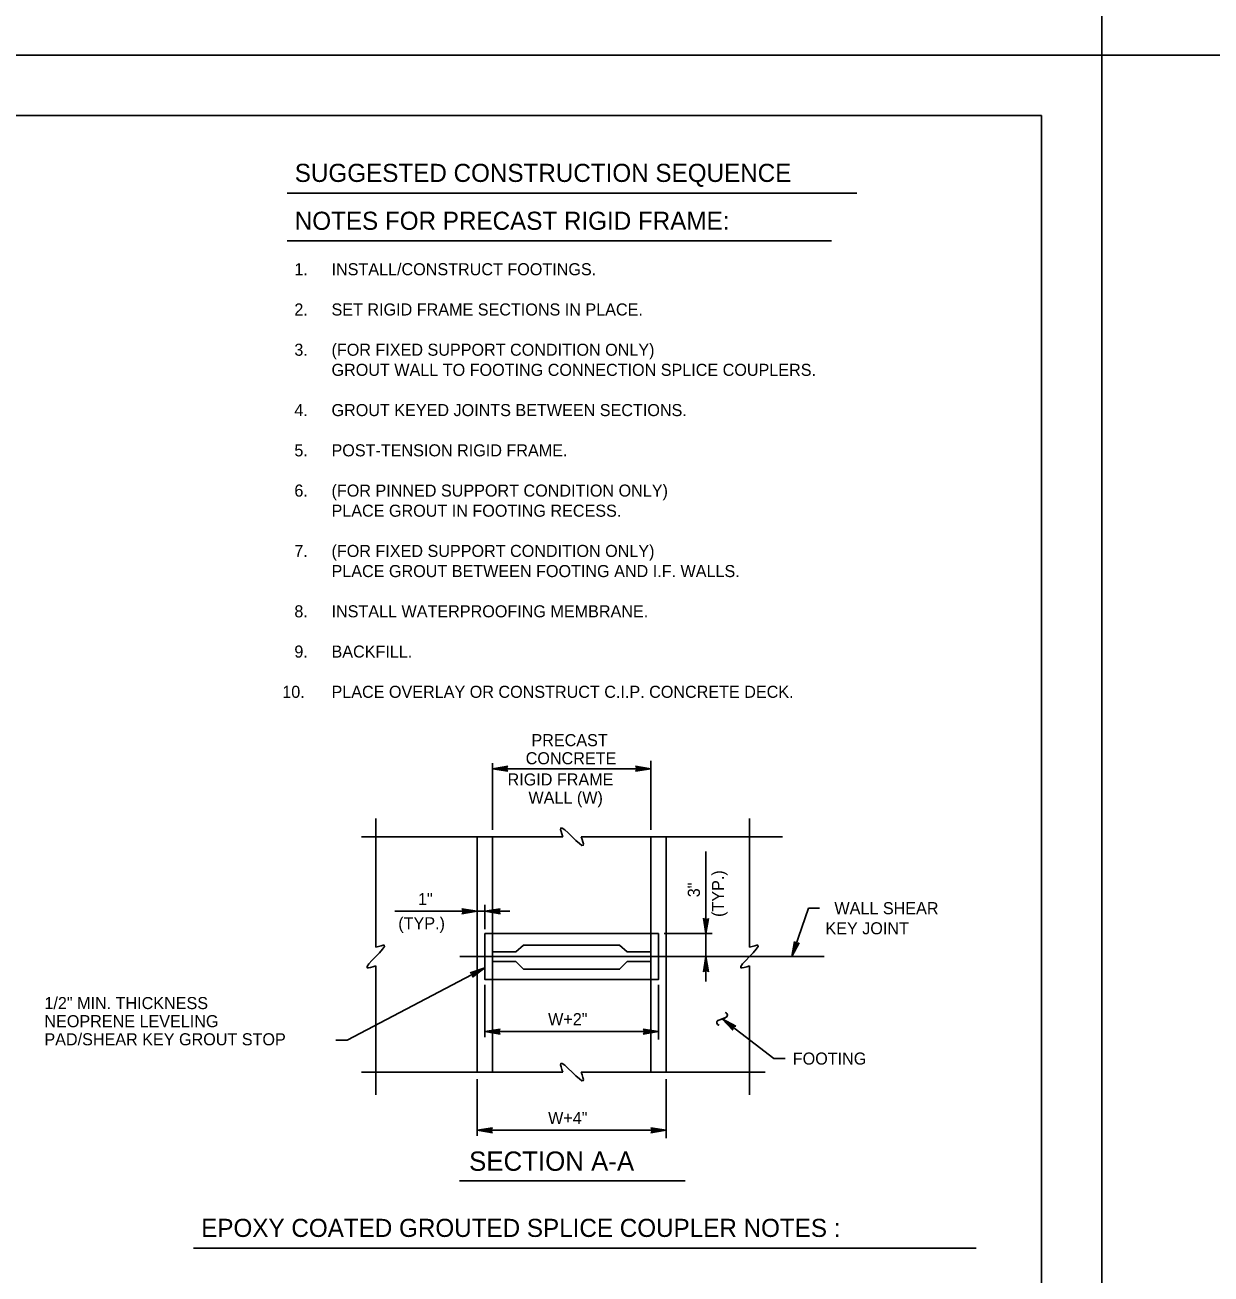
# Model space of a CAD drawing. Extents: x 641328 to 643024, y 298283 to 300065.
# Drawn here: x 641901 to 642195.6, y 299168.4 to 299478.8 of the extents above; entities that cross this region are included whole.
import ezdxf

# ---------------------------------------------------------------- set-up
doc = ezdxf.new("R2010")
doc.units = 0
for name, color, linetype in [('2', 7, 'Continuous'), ('PLT-BNDY', 7, 'Continuous'), ('S-ANNO-DIMENSION-PROP', 7, 'Continuous'), ('S-BRDG-CNTR-N', 7, 'Continuous')]:
    doc.layers.add(name, color=color, linetype=linetype)

msp = doc.modelspace()

# ---------------------------------------------------------------- linework, layer by layer
at = {"layer": '2'}
for p, q in [((641367.51, 299456.3), (642153.5, 299456.3)), ((642153.5, 299456.3), (642153.5, 298892.3)), ((641966.07, 299437.02), (642107.67, 299437.02)), ((641966.07, 299425.13), (642101.37, 299425.13)), ((642017.14, 299278.84), (642017.14, 299295.35)), ((642017.14, 299293.97), (642020.93, 299294.61)), ((642020.74, 299294.43), (642017.14, 299293.97)), ((642017.14, 299293.97), (642020.61, 299294.17)), ((642017.14, 299293.97), (642020.61, 299293.99)), ((642017.14, 299293.97), (642056.42, 299293.97)), ((642020.61, 299293.81), (642017.14, 299293.97)), ((642017.14, 299293.97), (642020.75, 299293.54)), ((642020.94, 299293.38), (642017.14, 299293.97)), ((642020.61, 299294.17), (642020.74, 299294.43)), ((642020.61, 299293.81), (642020.61, 299294.17)), ((642020.75, 299293.54), (642020.61, 299293.81)), ((642020.93, 299294.61), (642020.74, 299294.43)), ((642020.75, 299293.54), (642020.94, 299293.38)), ((642056.42, 299293.97), (642052.62, 299294.61)), ((642052.62, 299294.61), (642052.82, 299294.43)), ((642052.62, 299293.38), (642056.42, 299293.97)), ((642052.81, 299293.54), (642052.62, 299293.38)), ((642056.42, 299293.97), (642052.81, 299293.54)), ((642052.81, 299293.54), (642052.94, 299293.81)), ((642052.95, 299294.17), (642052.82, 299294.43)), ((642052.82, 299294.43), (642056.42, 299293.97)), ((642052.94, 299293.81), (642052.95, 299294.17)), ((642052.94, 299293.81), (642056.42, 299293.97)), ((642056.42, 299293.97), (642052.95, 299294.17)), ((642056.42, 299293.97), (642052.95, 299293.99)), ((642056.42, 299278.84), (642056.42, 299295.97)), ((641988.11, 299281.62), (641988.11, 299249.62)), ((642080.95, 299281.62), (642080.95, 299249.62)), ((642034.56, 299277.1), (641984.56, 299277.1)), ((642013.33, 299277.1), (642013.33, 299218.61)), ((642017.14, 299277.1), (642013.33, 299277.1)), ((642013.33, 299277.1), (642013.33, 299218.61)), ((642017.14, 299277.1), (642017.14, 299218.61)), ((642017.14, 299253.02), (642017.14, 299277.1)), ((642089.18, 299277.1), (642039.18, 299277.1)), ((642056.42, 299277.1), (642056.42, 299218.61)), ((642060.23, 299277.1), (642056.42, 299277.1)), ((642056.42, 299277.1), (642056.42, 299253.02)), ((642060.23, 299218.61), (642060.23, 299277.1)), ((642060.23, 299218.61), (642060.23, 299277.1)), ((642070.13, 299273.46), (642070.13, 299253.02)), ((642009.72, 299259.04), (642009.53, 299259.2)), ((642009.53, 299259.2), (642013.33, 299258.61)), ((642015.23, 299260.16), (642015.23, 299254.14)), ((642019.03, 299259.2), (642015.23, 299258.61)), ((642018.84, 299259.04), (642019.03, 299259.2)), ((642091.45, 299247.31), (642095.6, 299259.37)), ((642095.6, 299259.37), (642098.38, 299259.37)), ((641992.89, 299258.61), (642013.33, 299258.61)), ((642013.33, 299258.61), (642009.53, 299257.98)), ((642009.53, 299257.98), (642009.73, 299258.16)), ((642009.72, 299259.04), (642009.85, 299258.78)), ((642013.33, 299258.61), (642009.72, 299259.04)), ((642009.73, 299258.16), (642013.33, 299258.61)), ((642009.86, 299258.42), (642009.73, 299258.16)), ((642009.85, 299258.78), (642013.33, 299258.61)), ((642009.85, 299258.78), (642009.86, 299258.42)), ((642013.33, 299258.61), (642009.86, 299258.42)), ((642013.33, 299258.61), (642009.86, 299258.6)), ((642013.33, 299258.61), (642021.42, 299258.61)), ((642015.23, 299258.61), (642018.84, 299259.04)), ((642018.71, 299258.78), (642015.23, 299258.61)), ((642015.23, 299258.61), (642018.7, 299258.42)), ((642018.83, 299258.16), (642015.23, 299258.61)), ((642015.23, 299258.61), (642019.03, 299257.98)), ((642015.23, 299258.61), (642018.71, 299258.6)), ((642018.71, 299258.78), (642018.7, 299258.42)), ((642018.7, 299258.42), (642018.83, 299258.16)), ((642018.84, 299259.04), (642018.71, 299258.78)), ((642019.03, 299257.98), (642018.83, 299258.16)), ((642069.7, 299256.63), (642069.54, 299256.83)), ((642069.54, 299256.83), (642070.13, 299253.02)), ((642069.7, 299256.63), (642069.96, 299256.5)), ((642070.13, 299253.02), (642069.7, 299256.63)), ((642069.96, 299256.5), (642070.13, 299253.02)), ((642069.96, 299256.5), (642070.33, 299256.5)), ((642070.13, 299253.02), (642070.76, 299256.82)), ((642070.59, 299256.62), (642070.13, 299253.02)), ((642070.13, 299253.02), (642070.33, 299256.5)), ((642070.13, 299253.02), (642070.14, 299256.5)), ((642070.33, 299256.5), (642070.59, 299256.62)), ((642070.76, 299256.82), (642070.59, 299256.62)), ((642017.04, 299253.02), (642056.42, 299253.02)), ((642071.68, 299253.02), (642059.79, 299253.02)), ((642070.13, 299253.02), (642070.13, 299241.12)), ((642092.11, 299251.1), (642091.45, 299247.31)), ((642091.45, 299247.31), (642092.2, 299250.87)), ((642091.45, 299247.31), (642093.27, 299250.7)), ((642092.41, 299250.65), (642091.45, 299247.31)), ((642091.45, 299247.31), (642092.58, 299250.59)), ((642093.04, 299250.57), (642091.45, 299247.31)), ((642091.45, 299247.31), (642092.75, 299250.53)), ((642092.2, 299250.87), (642092.11, 299251.1)), ((642092.2, 299250.87), (642092.41, 299250.65)), ((642092.41, 299250.65), (642092.75, 299250.53)), ((642092.75, 299250.53), (642093.04, 299250.57)), ((642093.27, 299250.7), (642093.04, 299250.57)), ((642069.54, 299243.51), (642070.13, 299247.31)), ((642070.13, 299247.31), (642069.7, 299243.7)), ((642069.96, 299243.84), (642070.13, 299247.31)), ((642070.13, 299247.31), (642070.33, 299243.84)), ((642070.59, 299243.71), (642070.13, 299247.31)), ((642070.13, 299247.31), (642070.76, 299243.51)), ((642070.13, 299247.31), (642070.14, 299243.84)), ((642089.46, 299247.31), (642093.92, 299247.31)), ((642015.23, 299244.53), (641980.98, 299226.58)), ((641988.11, 299245), (641988.11, 299213)), ((642015.23, 299244.53), (642011.58, 299243.31)), ((642011.84, 299243.25), (642015.23, 299244.53)), ((642015.23, 299244.53), (642012.07, 299243.08)), ((642012.15, 299242.23), (642015.23, 299244.53)), ((642015.23, 299244.53), (642012.16, 299242.92)), ((642012.24, 299242.76), (642015.23, 299244.53)), ((642015.23, 299244.53), (642012.24, 299242.46)), ((642069.7, 299243.7), (642069.54, 299243.51)), ((642069.7, 299243.7), (642069.96, 299243.84)), ((642069.96, 299243.84), (642070.33, 299243.84)), ((642070.33, 299243.84), (642070.59, 299243.71)), ((642070.76, 299243.51), (642070.59, 299243.71)), ((642080.95, 299245), (642080.95, 299213)), ((642011.58, 299243.31), (642011.84, 299243.25)), ((642012.07, 299243.08), (642011.84, 299243.25)), ((642012.24, 299242.76), (642012.07, 299243.08)), ((642012.24, 299242.46), (642012.15, 299242.23)), ((642012.24, 299242.46), (642012.24, 299242.76)), ((642017.14, 299241.59), (642056.42, 299241.59)), ((642017.14, 299218.61), (642017.14, 299241.59)), ((642056.42, 299241.59), (642056.42, 299218.61)), ((642015.23, 299240.3), (642015.23, 299227.31)), ((642058.32, 299240.3), (642058.32, 299226.68)), ((642074.16, 299231.84), (642087.04, 299221.99)), ((642076.81, 299229.59), (642074.16, 299231.84)), ((642074.16, 299231.84), (642076.75, 299229.29)), ((642076.81, 299229.05), (642074.16, 299231.84)), ((642074.16, 299231.84), (642077.02, 299229.88)), ((642077.29, 299230), (642074.16, 299231.84)), ((642074.16, 299231.84), (642077.55, 299230.02)), ((642074.16, 299231.84), (642076.92, 299229.73)), ((642019.03, 299229.27), (642015.23, 299228.68)), ((642015.23, 299228.68), (642018.84, 299229.11)), ((642018.71, 299228.85), (642015.23, 299228.68)), ((642015.23, 299228.68), (642058.32, 299228.68)), ((642015.23, 299228.68), (642018.7, 299228.49)), ((642018.83, 299228.23), (642015.23, 299228.68)), ((642015.23, 299228.68), (642019.03, 299228.05)), ((642015.23, 299228.68), (642018.71, 299228.67)), ((642018.71, 299228.85), (642018.7, 299228.49)), ((642018.7, 299228.49), (642018.83, 299228.23)), ((642018.84, 299229.11), (642018.71, 299228.85)), ((642019.03, 299228.05), (642018.83, 299228.23)), ((642018.84, 299229.11), (642019.03, 299229.27)), ((642054.71, 299229.11), (642054.52, 299229.27)), ((642054.52, 299229.27), (642058.32, 299228.68)), ((642058.32, 299228.68), (642054.53, 299228.05)), ((642054.53, 299228.05), (642054.72, 299228.23)), ((642054.71, 299229.11), (642054.85, 299228.85)), ((642058.32, 299228.68), (642054.71, 299229.11)), ((642054.72, 299228.23), (642058.32, 299228.68)), ((642054.85, 299228.49), (642054.72, 299228.23)), ((642054.85, 299228.85), (642058.32, 299228.68)), ((642054.85, 299228.85), (642054.85, 299228.49)), ((642058.32, 299228.68), (642054.85, 299228.49)), ((642058.32, 299228.68), (642054.85, 299228.67)), ((642076.75, 299229.29), (642076.81, 299229.59)), ((642076.75, 299229.29), (642076.81, 299229.05)), ((642076.81, 299229.59), (642077.02, 299229.88)), ((642077.02, 299229.88), (642077.29, 299230)), ((642077.55, 299230.02), (642077.29, 299230)), ((641980.98, 299226.58), (641978.2, 299226.58)), ((642087.04, 299221.99), (642089.82, 299221.99)), ((642034.56, 299218.61), (641984.56, 299218.61)), ((642013.33, 299218.61), (642017.14, 299218.61)), ((642013.33, 299216.86), (642013.33, 299202.78)), ((642084.88, 299218.61), (642039.18, 299218.61)), ((642056.42, 299218.61), (642060.23, 299218.61)), ((642060.23, 299216.86), (642060.23, 299202.16)), ((642017.13, 299204.75), (642013.33, 299204.16)), ((642013.33, 299204.16), (642016.94, 299204.59)), ((642016.8, 299204.32), (642013.33, 299204.16)), ((642013.33, 299204.16), (642060.23, 299204.16)), ((642013.33, 299204.16), (642016.8, 299203.96)), ((642016.93, 299203.7), (642013.33, 299204.16)), ((642013.33, 299204.16), (642017.12, 299203.52)), ((642013.33, 299204.16), (642016.8, 299204.14)), ((642016.94, 299204.59), (642016.8, 299204.32)), ((642016.8, 299204.32), (642016.8, 299203.96)), ((642016.8, 299203.96), (642016.93, 299203.7)), ((642017.12, 299203.52), (642016.93, 299203.7)), ((642016.94, 299204.59), (642017.13, 299204.75)), ((642056.62, 299204.59), (642056.43, 299204.75)), ((642056.43, 299204.75), (642060.23, 299204.16)), ((642060.23, 299204.16), (642056.43, 299203.52)), ((642056.43, 299203.52), (642056.63, 299203.7)), ((642056.62, 299204.59), (642056.75, 299204.32)), ((642060.23, 299204.16), (642056.62, 299204.59)), ((642056.63, 299203.7), (642060.23, 299204.16)), ((642056.76, 299203.96), (642056.63, 299203.7)), ((642056.75, 299204.32), (642060.23, 299204.16)), ((642056.75, 299204.32), (642056.76, 299203.96)), ((642060.23, 299204.16), (642056.76, 299203.96)), ((642060.23, 299204.16), (642056.76, 299204.14)), ((642008.92, 299191.61), (642065, 299191.61)), ((641942.82, 299174.89), (642137.26, 299174.89))]:
    msp.add_line(p, q, dxfattribs=at)
for points in [[(642017.14, 299253.02), (642015.23, 299253.02), (642015.23, 299241.59), (642017.14, 299241.59)], [(642017.14, 299241.59), (642015.23, 299241.59), (642015.23, 299253.02), (642017.14, 299253.02)], [(642056.42, 299253.02), (642058.32, 299253.02), (642058.32, 299241.59), (642056.42, 299241.59)], [(642056.42, 299253.02), (642058.32, 299253.02), (642058.32, 299241.59), (642056.42, 299241.59)], [(642017.14, 299248.54), (642022.95, 299248.54), (642024.85, 299250.19), (642048.7, 299250.19), (642050.61, 299248.54), (642056.42, 299248.54)], [(642056.42, 299246.08), (642050.61, 299246.08), (642048.7, 299244.18), (642024.85, 299244.18), (642022.95, 299246.08), (642017.14, 299246.08)], [(642013.33, 299218.61), (642013.33, 299218.61)], [(642056.42, 299218.61), (642056.42, 299218.61)], [(642060.23, 299218.61), (642060.23, 299218.61)]]:
    msp.add_lwpolyline(points, dxfattribs=at)
for points in [[(642034.56, 299277.1), (642034.06, 299279.23), (642039.68, 299274.98), (642039.18, 299277.1)], [(641988.11, 299245), (641985.98, 299244.5), (641990.23, 299250.12), (641988.11, 299249.62)], [(642080.95, 299245), (642078.82, 299244.5), (642083.07, 299250.12), (642080.95, 299249.62)], [(642034.56, 299218.61), (642034.06, 299220.74), (642039.68, 299216.49), (642039.18, 299218.61)]]:
    msp.add_spline(points, degree=3, dxfattribs=at)
at = {"layer": 'PLT-BNDY'}
for points in [[(641327.51, 300065.3), (642168.51, 300065.3), (642168.51, 299471.3), (641327.51, 299471.3)], [(642168.51, 300065.3), (643009.51, 300065.3), (643009.51, 299471.3), (642168.51, 299471.3)], [(641327.51, 299471.3), (642168.51, 299471.3), (642168.51, 298877.3), (641327.51, 298877.3)], [(642168.51, 299471.3), (643009.51, 299471.3), (643009.51, 298877.3), (642168.51, 298877.3)]]:
    msp.add_lwpolyline(points, close=True, dxfattribs=at)
at = {"layer": 'S-ANNO-DIMENSION-PROP'}
for p, q in [((642074.99, 299232.15), (642073.33, 299231.53)), ((642074.99, 299232.14), (642073.33, 299231.54))]:
    msp.add_line(p, q, dxfattribs=at)
for centre, start, end in [((642073.51, 299230.91), 106.5891, 259.1215), ((642073.52, 299230.9), 106.7859, 259.3183), ((642074.8, 299232.78), 286.7859, 79.3183), ((642074.8, 299232.77), 286.5891, 79.1215)]:
    msp.add_arc(centre, 0.659, start, end, dxfattribs=at)
at = {"layer": 'S-BRDG-CNTR-N'}
msp.add_line((642008.98, 299247.31), (642099.54, 299247.31), dxfattribs=at)

# ---------------------------------------------------------------- texts
at = {"layer": '2'}
for s, height, p in [('SUGGESTED CONSTRUCTION SEQUENCE', 4.5, (641967.99, 299439.8)), ('NOTES FOR PRECAST RIGID FRAME:', 4.5, (641967.99, 299427.9)), ('1.', 3, (641967.89, 299416.61)), ('INSTALL/CONSTRUCT FOOTINGS.', 3, (641977.12, 299416.61)), ('2.', 3, (641967.89, 299406.61)), ('SET RIGID FRAME SECTIONS IN PLACE.', 3, (641977.12, 299406.61)), ('3.', 3, (641967.89, 299396.61)), ('(FOR FIXED SUPPORT CONDITION ONLY)', 3, (641977.12, 299396.61)), ('GROUT WALL TO FOOTING CONNECTION SPLICE COUPLERS.', 3, (641977.12, 299391.61)), ('4.', 3, (641967.89, 299381.61)), ('GROUT KEYED JOINTS BETWEEN SECTIONS.', 3, (641977.12, 299381.61)), ('5.', 3, (641967.89, 299371.61)), ('POST-TENSION RIGID FRAME.', 3, (641977.12, 299371.61)), ('6.', 3, (641967.89, 299361.61)), ('(FOR PINNED SUPPORT CONDITION ONLY)', 3, (641977.12, 299361.61)), ('PLACE GROUT IN FOOTING RECESS.', 3, (641977.12, 299356.61)), ('7.', 3, (641967.89, 299346.61)), ('(FOR FIXED SUPPORT CONDITION ONLY)', 3, (641977.12, 299346.61)), ('PLACE GROUT BETWEEN FOOTING AND I.F. WALLS.', 3, (641977.12, 299341.61)), ('8.', 3, (641967.89, 299331.61)), ('INSTALL WATERPROOFING MEMBRANE.', 3, (641977.12, 299331.61)), ('9.', 3, (641967.89, 299321.61)), ('BACKFILL.', 3, (641977.12, 299321.61)), ('10.', 3, (641964.89, 299311.61)), ('PLACE OVERLAY OR CONSTRUCT C.I.P. CONCRETE DECK.', 3, (641977.12, 299311.61)), ('PRECAST', 3, (642026.79, 299299.6)), ('CONCRETE', 3, (642025.36, 299295.1)), ('RIGID FRAME', 3, (642020.86, 299289.83)), ('WALL (W)', 3, (642026.04, 299285.33)), ('1"', 3, (641998.6, 299260.11)), ('  WALL SHEAR', 3, (642099.83, 299257.85)), ('(TYP.)', 3, (641993.71, 299254.11)), ('KEY JOINT', 3, (642099.83, 299252.85)), ('1/2" MIN. THICKNESS ', 3, (641905.79, 299234.27)), ('NEOPRENE LEVELING', 3, (641905.79, 299229.77)), ('W+2"', 3, (642030.93, 299230.26)), ('PAD/SHEAR KEY GROUT STOP', 3, (641905.79, 299225.27)), ('FOOTING', 3, (642091.72, 299220.48)), ('W+4"', 3, (642030.93, 299205.73)), ('SECTION A-A', 4.8, (642011.3, 299194.09)), ('EPOXY COATED GROUTED SPLICE COUPLER NOTES :', 4.5, (641944.74, 299177.66))]:
    msp.add_text(s, height=height, dxfattribs=at).set_placement(p)
for s, p in [('(TYP.)', (642074.63, 299257.17)), ('3"', (642068.63, 299262.06))]:
    msp.add_text(s, height=3, rotation=90, dxfattribs=at).set_placement(p)

doc.saveas('drawing.dxf')
